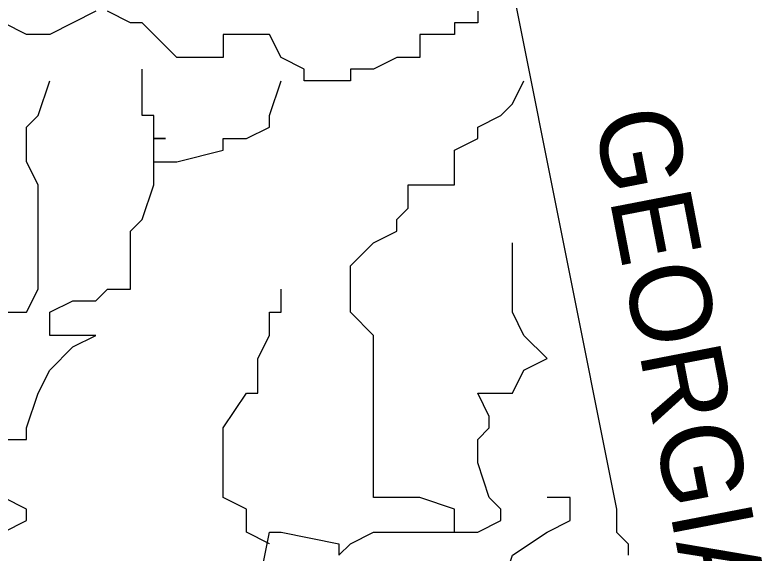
# Model space of a CAD drawing. Extents: x 2193008 to 2198143, y 1236112 to 1237864.
# Drawn here: x 2195042.237 to 2195045.645, y 1237128.035 to 1237130.482 of the extents above; entities that cross this region are included whole.
import ezdxf

# ---------------------------------------------------------------- set-up
doc = ezdxf.new("R2010")
doc.units = 0
doc.layers.add('great seal', color=7, linetype='Continuous')

msp = doc.modelspace()

# ---------------------------------------------------------------- linework, layer by layer
at = {"layer": 'great seal'}
msp.add_line((2195043.3936, 1237128.0819), (2195043.3936, 1237128.0819), dxfattribs=at)
msp.add_line((2195043.3936, 1237128.0819), (2195043.3936, 1237128.0819), dxfattribs=at)
msp.add_line((2195043.3936, 1237128.0819), (2195043.3936, 1237128.0819), dxfattribs=at)
msp.add_line((2195043.3936, 1237128.0819), (2195043.3936, 1237128.0819), dxfattribs=at)
msp.add_line((2195043.3936, 1237128.0819), (2195043.3936, 1237128.0819), dxfattribs=at)
msp.add_line((2195043.3936, 1237128.0819), (2195043.3936, 1237128.0819), dxfattribs=at)
for points in [[(2195044.4972, 1237130.6045), (2195044.9702, 1237128.2396), (2195044.9702, 1237128.1345), (2195045.0227, 1237128.0819), (2195045.0227, 1237128.0294)], [(2195044.4972, 1237130.6045), (2195044.9702, 1237128.2396), (2195044.9702, 1237128.1345), (2195045.0227, 1237128.0819), (2195045.0227, 1237128.0294)], [(2195044.4972, 1237130.6045), (2195044.9702, 1237128.2396), (2195044.9702, 1237128.1345), (2195045.0227, 1237128.0819), (2195045.0227, 1237128.0294)], [(2195042.6053, 1237130.4994), (2195042.5002, 1237130.4468), (2195042.5002, 1237130.4468), (2195042.3951, 1237130.3942), (2195042.3425, 1237130.3942), (2195042.29, 1237130.3942), (2195042.1849, 1237130.4468), (2195042.1849, 1237130.4468), (2195042.1849, 1237130.4468), (2195042.1323, 1237130.4468), (2195042.1323, 1237130.4468), (2195042.1323, 1237130.4468), (2195042.1323, 1237130.4994)], [(2195042.6053, 1237130.4994), (2195042.5002, 1237130.4468), (2195042.5002, 1237130.4468), (2195042.3951, 1237130.3942), (2195042.3425, 1237130.3942), (2195042.29, 1237130.3942), (2195042.1849, 1237130.4468), (2195042.1849, 1237130.4468), (2195042.1849, 1237130.4468), (2195042.1323, 1237130.4468), (2195042.1323, 1237130.4468), (2195042.1323, 1237130.4468), (2195042.1323, 1237130.4994)], [(2195042.6053, 1237130.4994), (2195042.5002, 1237130.4468), (2195042.5002, 1237130.4468), (2195042.3951, 1237130.3942), (2195042.3425, 1237130.3942), (2195042.29, 1237130.3942), (2195042.1849, 1237130.4468), (2195042.1849, 1237130.4468), (2195042.1849, 1237130.4468), (2195042.1323, 1237130.4468), (2195042.1323, 1237130.4468), (2195042.1323, 1237130.4468), (2195042.1323, 1237130.4994)], [(2195044.3395, 1237130.4994), (2195044.3395, 1237130.4468), (2195044.3395, 1237130.4468), (2195044.2344, 1237130.4468), (2195044.2344, 1237130.4468), (2195044.2344, 1237130.3942), (2195044.0768, 1237130.3942), (2195044.0768, 1237130.2891), (2195043.9717, 1237130.2891), (2195043.8665, 1237130.2366), (2195043.814, 1237130.2366), (2195043.7614, 1237130.2366), (2195043.7614, 1237130.184), (2195043.7089, 1237130.184), (2195043.7089, 1237130.184), (2195043.5512, 1237130.184), (2195043.5512, 1237130.184), (2195043.5512, 1237130.2366), (2195043.4461, 1237130.2891), (2195043.3936, 1237130.3942), (2195043.3936, 1237130.3942), (2195043.2885, 1237130.3942), (2195043.1834, 1237130.3942), (2195043.1834, 1237130.2891), (2195042.9732, 1237130.2891), (2195042.868, 1237130.3942), (2195042.8155, 1237130.4468), (2195042.7629, 1237130.4468), (2195042.6578, 1237130.4994)], [(2195044.3395, 1237130.4994), (2195044.3395, 1237130.4468), (2195044.3395, 1237130.4468), (2195044.2344, 1237130.4468), (2195044.2344, 1237130.4468), (2195044.2344, 1237130.3942), (2195044.0768, 1237130.3942), (2195044.0768, 1237130.2891), (2195043.9717, 1237130.2891), (2195043.8665, 1237130.2366), (2195043.814, 1237130.2366), (2195043.7614, 1237130.2366), (2195043.7614, 1237130.184), (2195043.7089, 1237130.184), (2195043.7089, 1237130.184), (2195043.5512, 1237130.184), (2195043.5512, 1237130.184), (2195043.5512, 1237130.2366), (2195043.4461, 1237130.2891), (2195043.3936, 1237130.3942), (2195043.3936, 1237130.3942), (2195043.2885, 1237130.3942), (2195043.1834, 1237130.3942), (2195043.1834, 1237130.2891), (2195042.9732, 1237130.2891), (2195042.868, 1237130.3942), (2195042.8155, 1237130.4468), (2195042.7629, 1237130.4468), (2195042.6578, 1237130.4994)], [(2195044.3395, 1237130.4994), (2195044.3395, 1237130.4468), (2195044.3395, 1237130.4468), (2195044.2344, 1237130.4468), (2195044.2344, 1237130.4468), (2195044.2344, 1237130.3942), (2195044.0768, 1237130.3942), (2195044.0768, 1237130.2891), (2195043.9717, 1237130.2891), (2195043.8665, 1237130.2366), (2195043.814, 1237130.2366), (2195043.7614, 1237130.2366), (2195043.7614, 1237130.184), (2195043.7089, 1237130.184), (2195043.7089, 1237130.184), (2195043.5512, 1237130.184), (2195043.5512, 1237130.184), (2195043.5512, 1237130.2366), (2195043.4461, 1237130.2891), (2195043.3936, 1237130.3942), (2195043.3936, 1237130.3942), (2195043.2885, 1237130.3942), (2195043.1834, 1237130.3942), (2195043.1834, 1237130.2891), (2195042.9732, 1237130.2891), (2195042.868, 1237130.3942), (2195042.8155, 1237130.4468), (2195042.7629, 1237130.4468), (2195042.6578, 1237130.4994)], [(2195042.868, 1237129.8162), (2195042.868, 1237129.8687), (2195042.868, 1237129.9213), (2195042.9206, 1237129.9213), (2195042.868, 1237129.9213), (2195042.868, 1237129.9738), (2195042.868, 1237130.0264), (2195042.8155, 1237130.0264), (2195042.8155, 1237130.0789), (2195042.8155, 1237130.184), (2195042.8155, 1237130.2366)], [(2195042.868, 1237129.8162), (2195042.868, 1237129.8687), (2195042.868, 1237129.9213), (2195042.9206, 1237129.9213), (2195042.868, 1237129.9213), (2195042.868, 1237129.9738), (2195042.868, 1237130.0264), (2195042.8155, 1237130.0264), (2195042.8155, 1237130.0789), (2195042.8155, 1237130.184), (2195042.8155, 1237130.2366)], [(2195042.868, 1237129.8162), (2195042.868, 1237129.8687), (2195042.868, 1237129.9213), (2195042.9206, 1237129.9213), (2195042.868, 1237129.9213), (2195042.868, 1237129.9738), (2195042.868, 1237130.0264), (2195042.8155, 1237130.0264), (2195042.8155, 1237130.0789), (2195042.8155, 1237130.184), (2195042.8155, 1237130.2366)], [(2195042.0798, 1237128.7651), (2195042.0798, 1237128.8702), (2195042.0798, 1237128.9228), (2195042.0798, 1237129.0279), (2195042.1323, 1237129.0279), (2195042.1849, 1237129.133), (2195042.29, 1237129.133), (2195042.3425, 1237129.2381), (2195042.3425, 1237129.4483), (2195042.3425, 1237129.5534), (2195042.3425, 1237129.606), (2195042.3425, 1237129.7111), (2195042.29, 1237129.8162), (2195042.29, 1237129.9213), (2195042.29, 1237129.9738), (2195042.3425, 1237130.0264), (2195042.3951, 1237130.184)], [(2195042.0798, 1237128.7651), (2195042.0798, 1237128.8702), (2195042.0798, 1237128.9228), (2195042.0798, 1237129.0279), (2195042.1323, 1237129.0279), (2195042.1849, 1237129.133), (2195042.29, 1237129.133), (2195042.3425, 1237129.2381), (2195042.3425, 1237129.4483), (2195042.3425, 1237129.5534), (2195042.3425, 1237129.606), (2195042.3425, 1237129.7111), (2195042.29, 1237129.8162), (2195042.29, 1237129.9213), (2195042.29, 1237129.9738), (2195042.3425, 1237130.0264), (2195042.3951, 1237130.184)], [(2195042.0798, 1237128.7651), (2195042.0798, 1237128.8702), (2195042.0798, 1237128.9228), (2195042.0798, 1237129.0279), (2195042.1323, 1237129.0279), (2195042.1849, 1237129.133), (2195042.29, 1237129.133), (2195042.3425, 1237129.2381), (2195042.3425, 1237129.4483), (2195042.3425, 1237129.5534), (2195042.3425, 1237129.606), (2195042.3425, 1237129.7111), (2195042.29, 1237129.8162), (2195042.29, 1237129.9213), (2195042.29, 1237129.9738), (2195042.3425, 1237130.0264), (2195042.3951, 1237130.184)], [(2195042.1849, 1237128.5549), (2195042.29, 1237128.5549), (2195042.29, 1237128.6075), (2195042.3425, 1237128.7651), (2195042.3951, 1237128.8702), (2195042.5002, 1237128.9753), (2195042.6053, 1237129.0279), (2195042.5002, 1237129.0279), (2195042.3951, 1237129.0279), (2195042.3951, 1237129.133), (2195042.5002, 1237129.1855), (2195042.5002, 1237129.1855), (2195042.6053, 1237129.1855), (2195042.6578, 1237129.2381), (2195042.6578, 1237129.2381), (2195042.7629, 1237129.2381), (2195042.7629, 1237129.3432), (2195042.7629, 1237129.4483), (2195042.7629, 1237129.4483), (2195042.7629, 1237129.5008), (2195042.8155, 1237129.5534), (2195042.868, 1237129.7111), (2195042.868, 1237129.7111), (2195042.868, 1237129.8162), (2195042.9206, 1237129.8162), (2195042.9732, 1237129.8162), (2195042.9732, 1237129.8162), (2195043.1834, 1237129.8687), (2195043.1834, 1237129.9213), (2195043.2885, 1237129.9213), (2195043.3936, 1237129.9738), (2195043.3936, 1237130.0264), (2195043.4461, 1237130.184)], [(2195042.1849, 1237128.5549), (2195042.29, 1237128.5549), (2195042.29, 1237128.6075), (2195042.3425, 1237128.7651), (2195042.3951, 1237128.8702), (2195042.5002, 1237128.9753), (2195042.6053, 1237129.0279), (2195042.5002, 1237129.0279), (2195042.3951, 1237129.0279), (2195042.3951, 1237129.133), (2195042.5002, 1237129.1855), (2195042.5002, 1237129.1855), (2195042.6053, 1237129.1855), (2195042.6578, 1237129.2381), (2195042.6578, 1237129.2381), (2195042.7629, 1237129.2381), (2195042.7629, 1237129.3432), (2195042.7629, 1237129.4483), (2195042.7629, 1237129.4483), (2195042.7629, 1237129.5008), (2195042.8155, 1237129.5534), (2195042.868, 1237129.7111), (2195042.868, 1237129.7111), (2195042.868, 1237129.8162), (2195042.9206, 1237129.8162), (2195042.9732, 1237129.8162), (2195042.9732, 1237129.8162), (2195043.1834, 1237129.8687), (2195043.1834, 1237129.9213), (2195043.2885, 1237129.9213), (2195043.3936, 1237129.9738), (2195043.3936, 1237130.0264), (2195043.4461, 1237130.184)], [(2195042.1849, 1237128.5549), (2195042.29, 1237128.5549), (2195042.29, 1237128.6075), (2195042.3425, 1237128.7651), (2195042.3951, 1237128.8702), (2195042.5002, 1237128.9753), (2195042.6053, 1237129.0279), (2195042.5002, 1237129.0279), (2195042.3951, 1237129.0279), (2195042.3951, 1237129.133), (2195042.5002, 1237129.1855), (2195042.5002, 1237129.1855), (2195042.6053, 1237129.1855), (2195042.6578, 1237129.2381), (2195042.6578, 1237129.2381), (2195042.7629, 1237129.2381), (2195042.7629, 1237129.3432), (2195042.7629, 1237129.4483), (2195042.7629, 1237129.4483), (2195042.7629, 1237129.5008), (2195042.8155, 1237129.5534), (2195042.868, 1237129.7111), (2195042.868, 1237129.7111), (2195042.868, 1237129.8162), (2195042.9206, 1237129.8162), (2195042.9732, 1237129.8162), (2195042.9732, 1237129.8162), (2195043.1834, 1237129.8687), (2195043.1834, 1237129.9213), (2195043.2885, 1237129.9213), (2195043.3936, 1237129.9738), (2195043.3936, 1237130.0264), (2195043.4461, 1237130.184)], [(2195044.2344, 1237128.1345), (2195044.2344, 1237128.2396), (2195044.0768, 1237128.2921), (2195044.0242, 1237128.2921), (2195043.8665, 1237128.2921), (2195043.8665, 1237128.5549), (2195043.8665, 1237128.5549), (2195043.8665, 1237128.6075), (2195043.8665, 1237128.7651), (2195043.8665, 1237128.8702), (2195043.8665, 1237129.0279), (2195043.7614, 1237129.133), (2195043.7614, 1237129.3432), (2195043.8665, 1237129.4483), (2195043.9717, 1237129.5008), (2195043.9717, 1237129.5534), (2195044.0242, 1237129.606), (2195044.0242, 1237129.7111), (2195044.2344, 1237129.7111), (2195044.2344, 1237129.8162), (2195044.2344, 1237129.8687), (2195044.3395, 1237129.9213), (2195044.3395, 1237129.9738), (2195044.4446, 1237130.0264), (2195044.4972, 1237130.0789), (2195044.5497, 1237130.184)], [(2195044.2344, 1237128.1345), (2195044.2344, 1237128.2396), (2195044.0768, 1237128.2921), (2195044.0242, 1237128.2921), (2195043.8665, 1237128.2921), (2195043.8665, 1237128.5549), (2195043.8665, 1237128.5549), (2195043.8665, 1237128.6075), (2195043.8665, 1237128.7651), (2195043.8665, 1237128.8702), (2195043.8665, 1237129.0279), (2195043.7614, 1237129.133), (2195043.7614, 1237129.3432), (2195043.8665, 1237129.4483), (2195043.9717, 1237129.5008), (2195043.9717, 1237129.5534), (2195044.0242, 1237129.606), (2195044.0242, 1237129.7111), (2195044.2344, 1237129.7111), (2195044.2344, 1237129.8162), (2195044.2344, 1237129.8687), (2195044.3395, 1237129.9213), (2195044.3395, 1237129.9738), (2195044.4446, 1237130.0264), (2195044.4972, 1237130.0789), (2195044.5497, 1237130.184)], [(2195044.2344, 1237128.1345), (2195044.2344, 1237128.2396), (2195044.0768, 1237128.2921), (2195044.0242, 1237128.2921), (2195043.8665, 1237128.2921), (2195043.8665, 1237128.5549), (2195043.8665, 1237128.5549), (2195043.8665, 1237128.6075), (2195043.8665, 1237128.7651), (2195043.8665, 1237128.8702), (2195043.8665, 1237129.0279), (2195043.7614, 1237129.133), (2195043.7614, 1237129.3432), (2195043.8665, 1237129.4483), (2195043.9717, 1237129.5008), (2195043.9717, 1237129.5534), (2195044.0242, 1237129.606), (2195044.0242, 1237129.7111), (2195044.2344, 1237129.7111), (2195044.2344, 1237129.8162), (2195044.2344, 1237129.8687), (2195044.3395, 1237129.9213), (2195044.3395, 1237129.9738), (2195044.4446, 1237130.0264), (2195044.4972, 1237130.0789), (2195044.5497, 1237130.184)], [(2195043.341, 1237127.8717), (2195043.3936, 1237128.1345), (2195043.4461, 1237128.1345), (2195043.7089, 1237128.0819), (2195043.7089, 1237128.0294), (2195043.7614, 1237128.0819), (2195043.8665, 1237128.1345), (2195044.0242, 1237128.1345), (2195044.2344, 1237128.1345), (2195044.3395, 1237128.1345), (2195044.4446, 1237128.187), (2195044.4446, 1237128.2396), (2195044.3921, 1237128.2921), (2195044.3921, 1237128.2921), (2195044.3395, 1237128.4498), (2195044.3395, 1237128.5549), (2195044.3921, 1237128.6075), (2195044.3921, 1237128.66), (2195044.3395, 1237128.7651), (2195044.4972, 1237128.7651), (2195044.5497, 1237128.8702), (2195044.6548, 1237128.9228), (2195044.5497, 1237129.0279), (2195044.5497, 1237129.0279), (2195044.4972, 1237129.133), (2195044.4972, 1237129.2381), (2195044.4972, 1237129.4483)], [(2195043.341, 1237127.8717), (2195043.3936, 1237128.1345), (2195043.4461, 1237128.1345), (2195043.7089, 1237128.0819), (2195043.7089, 1237128.0294), (2195043.7614, 1237128.0819), (2195043.8665, 1237128.1345), (2195044.0242, 1237128.1345), (2195044.2344, 1237128.1345), (2195044.3395, 1237128.1345), (2195044.4446, 1237128.187), (2195044.4446, 1237128.2396), (2195044.3921, 1237128.2921), (2195044.3921, 1237128.2921), (2195044.3395, 1237128.4498), (2195044.3395, 1237128.5549), (2195044.3921, 1237128.6075), (2195044.3921, 1237128.66), (2195044.3395, 1237128.7651), (2195044.4972, 1237128.7651), (2195044.5497, 1237128.8702), (2195044.6548, 1237128.9228), (2195044.5497, 1237129.0279), (2195044.5497, 1237129.0279), (2195044.4972, 1237129.133), (2195044.4972, 1237129.2381), (2195044.4972, 1237129.4483)], [(2195043.341, 1237127.8717), (2195043.3936, 1237128.1345), (2195043.4461, 1237128.1345), (2195043.7089, 1237128.0819), (2195043.7089, 1237128.0294), (2195043.7614, 1237128.0819), (2195043.8665, 1237128.1345), (2195044.0242, 1237128.1345), (2195044.2344, 1237128.1345), (2195044.3395, 1237128.1345), (2195044.4446, 1237128.187), (2195044.4446, 1237128.2396), (2195044.3921, 1237128.2921), (2195044.3921, 1237128.2921), (2195044.3395, 1237128.4498), (2195044.3395, 1237128.5549), (2195044.3921, 1237128.6075), (2195044.3921, 1237128.66), (2195044.3395, 1237128.7651), (2195044.4972, 1237128.7651), (2195044.5497, 1237128.8702), (2195044.6548, 1237128.9228), (2195044.5497, 1237129.0279), (2195044.5497, 1237129.0279), (2195044.4972, 1237129.133), (2195044.4972, 1237129.2381), (2195044.4972, 1237129.4483)], [(2195043.3936, 1237128.0819), (2195043.2885, 1237128.1345), (2195043.2885, 1237128.187), (2195043.2885, 1237128.2396), (2195043.1834, 1237128.2921), (2195043.1834, 1237128.4498), (2195043.1834, 1237128.5549), (2195043.1834, 1237128.6075), (2195043.1834, 1237128.6075), (2195043.2885, 1237128.7651), (2195043.341, 1237128.7651), (2195043.341, 1237128.9228), (2195043.3936, 1237129.0279), (2195043.3936, 1237129.0279), (2195043.3936, 1237129.133), (2195043.4461, 1237129.133), (2195043.4461, 1237129.2381)], [(2195043.3936, 1237128.0819), (2195043.2885, 1237128.1345), (2195043.2885, 1237128.187), (2195043.2885, 1237128.2396), (2195043.1834, 1237128.2921), (2195043.1834, 1237128.4498), (2195043.1834, 1237128.5549), (2195043.1834, 1237128.6075), (2195043.1834, 1237128.6075), (2195043.2885, 1237128.7651), (2195043.341, 1237128.7651), (2195043.341, 1237128.9228), (2195043.3936, 1237129.0279), (2195043.3936, 1237129.0279), (2195043.3936, 1237129.133), (2195043.4461, 1237129.133), (2195043.4461, 1237129.2381)], [(2195043.3936, 1237128.0819), (2195043.2885, 1237128.1345), (2195043.2885, 1237128.187), (2195043.2885, 1237128.2396), (2195043.1834, 1237128.2921), (2195043.1834, 1237128.4498), (2195043.1834, 1237128.5549), (2195043.1834, 1237128.6075), (2195043.1834, 1237128.6075), (2195043.2885, 1237128.7651), (2195043.341, 1237128.7651), (2195043.341, 1237128.9228), (2195043.3936, 1237129.0279), (2195043.3936, 1237129.0279), (2195043.3936, 1237129.133), (2195043.4461, 1237129.133), (2195043.4461, 1237129.2381)], [(2195042.1849, 1237128.1345), (2195042.29, 1237128.187), (2195042.29, 1237128.2396), (2195042.1849, 1237128.2921)], [(2195042.1849, 1237128.1345), (2195042.29, 1237128.187), (2195042.29, 1237128.2396), (2195042.1849, 1237128.2921)], [(2195042.1849, 1237128.1345), (2195042.29, 1237128.187), (2195042.29, 1237128.2396), (2195042.1849, 1237128.2921)], [(2195043.7089, 1237126.7156), (2195043.7089, 1237126.7156), (2195043.7089, 1237126.8732), (2195043.7614, 1237126.9258), (2195043.7614, 1237126.9783), (2195043.7614, 1237127.0834), (2195043.814, 1237127.0834), (2195043.8665, 1237127.1885), (2195044.0242, 1237127.2411), (2195044.0768, 1237127.3462), (2195044.2344, 1237127.3462), (2195044.2344, 1237127.4513), (2195044.3395, 1237127.6615), (2195044.3395, 1237127.7666), (2195044.3395, 1237127.7666), (2195044.3395, 1237127.8192), (2195044.3921, 1237127.8192), (2195044.4446, 1237127.8717), (2195044.4972, 1237128.0294), (2195044.6548, 1237128.1345), (2195044.7599, 1237128.187), (2195044.7599, 1237128.2396), (2195044.7599, 1237128.2921), (2195044.6548, 1237128.2921)], [(2195043.7089, 1237126.7156), (2195043.7089, 1237126.7156), (2195043.7089, 1237126.8732), (2195043.7614, 1237126.9258), (2195043.7614, 1237126.9783), (2195043.7614, 1237127.0834), (2195043.814, 1237127.0834), (2195043.8665, 1237127.1885), (2195044.0242, 1237127.2411), (2195044.0768, 1237127.3462), (2195044.2344, 1237127.3462), (2195044.2344, 1237127.4513), (2195044.3395, 1237127.6615), (2195044.3395, 1237127.7666), (2195044.3395, 1237127.7666), (2195044.3395, 1237127.8192), (2195044.3921, 1237127.8192), (2195044.4446, 1237127.8717), (2195044.4972, 1237128.0294), (2195044.6548, 1237128.1345), (2195044.7599, 1237128.187), (2195044.7599, 1237128.2396), (2195044.7599, 1237128.2921), (2195044.6548, 1237128.2921)], [(2195043.7089, 1237126.7156), (2195043.7089, 1237126.7156), (2195043.7089, 1237126.8732), (2195043.7614, 1237126.9258), (2195043.7614, 1237126.9783), (2195043.7614, 1237127.0834), (2195043.814, 1237127.0834), (2195043.8665, 1237127.1885), (2195044.0242, 1237127.2411), (2195044.0768, 1237127.3462), (2195044.2344, 1237127.3462), (2195044.2344, 1237127.4513), (2195044.3395, 1237127.6615), (2195044.3395, 1237127.7666), (2195044.3395, 1237127.7666), (2195044.3395, 1237127.8192), (2195044.3921, 1237127.8192), (2195044.4446, 1237127.8717), (2195044.4972, 1237128.0294), (2195044.6548, 1237128.1345), (2195044.7599, 1237128.187), (2195044.7599, 1237128.2396), (2195044.7599, 1237128.2921), (2195044.6548, 1237128.2921)]]:
    msp.add_lwpolyline(points, dxfattribs=at)
for radius in [4.5988, 4.5988, 4.5988, 4.4778, 4.4778, 4.4778, 3.5557, 3.5557, 3.5557, 3.4444, 3.4444, 3.4444]:
    msp.add_circle((2195043.3971, 1237128.0451), radius, dxfattribs=at)

# ---------------------------------------------------------------- texts
msp.add_text('GEORGIA', height=0.36892, rotation=280.9296, dxfattribs=at).set_placement((2195044.865, 1237130.0264))
msp.add_text('GEORGIA', height=0.36892, rotation=280.9296, dxfattribs=at).set_placement((2195044.865, 1237130.0264))
msp.add_text('GEORGIA', height=0.36892, rotation=280.9296, dxfattribs=at).set_placement((2195044.865, 1237130.0264))

doc.saveas('drawing.dxf')
